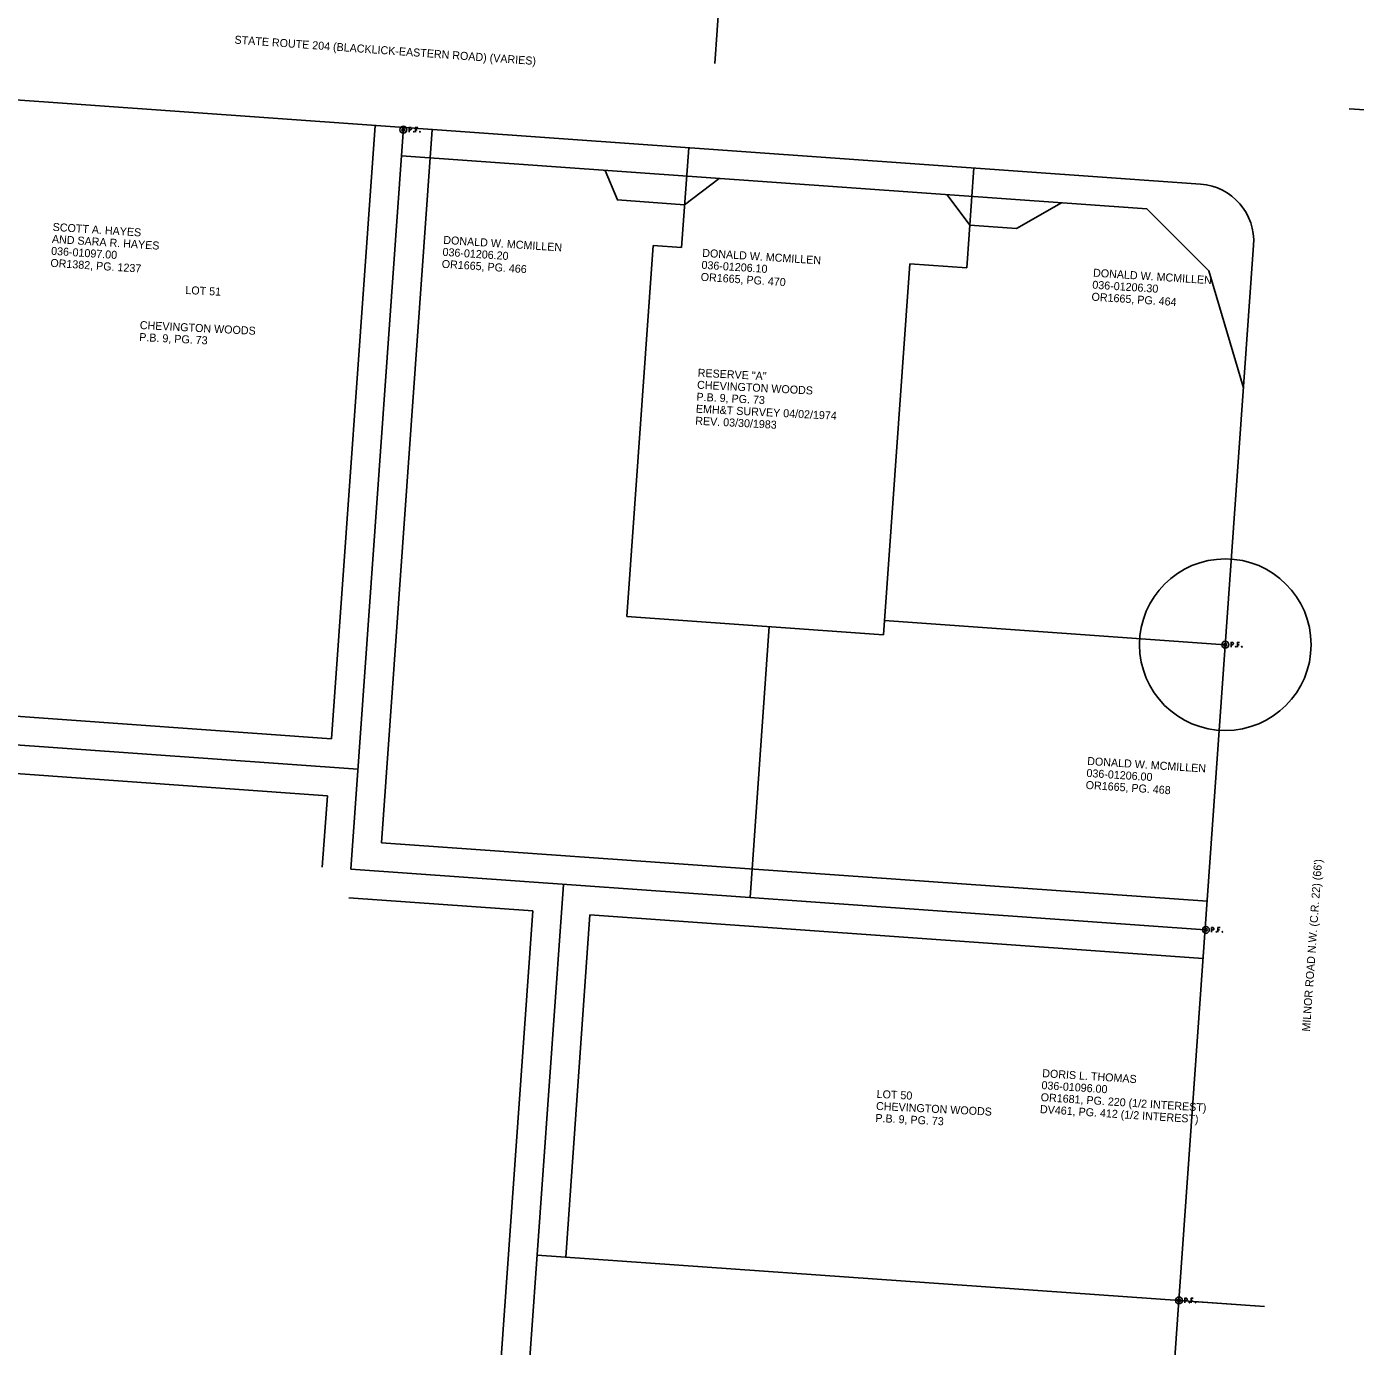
# Model space of a CAD drawing. Extents: x 1898254 to 1901377, y 701554 to 704886.
# Drawn here: x 1899353.1 to 1899817.9, y 702797.1 to 703258.5 of the extents above; entities that cross this region are included whole.
import ezdxf

# ---------------------------------------------------------------- set-up
doc = ezdxf.new("R2010")
doc.units = 0
for name, color, linetype in [('DV_X_Property_Line', 7, 'Continuous'), ('DV_X_Text', 7, 'Continuous'), ('RW_X_CL', 7, 'Continuous'), ('RW_X_Esmt_General', 7, 'Continuous'), ('RW_X_Esmt_SH', 7, 'Continuous'), ('RW_X_Fee_RW', 7, 'Continuous'), ('RW_X_Text', 7, 'Continuous'), ('SC_Scratch1', 7, 'Continuous'), ('SC_Scratch2', 7, 'Continuous'), ('SV_P_Mon_Cells_Set', 7, 'Continuous'), ('SV_X_Mon_Cells_Found', 7, 'Continuous'), ('VG_P_Cells', 7, 'Continuous')]:
    doc.layers.add(name, color=color, linetype=linetype)

msp = doc.modelspace()

# ---------------------------------------------------------------- linework, layer by layer
at = {"layer": 'DV_X_Property_Line'}
for p, q in [((1899466.52, 702963.89), (1899484.96, 703223.29)), ((1899582.23, 703181.28), (1899584.71, 703216.19)), ((1899681.98, 703174.19), (1899684.46, 703209.1)), ((1899563.03, 703052.28), (1899572.25, 703181.99)), ((1899582.23, 703181.28), (1899572.25, 703181.99)), ((1899652.8, 703045.9), (1899662.03, 703175.61)), ((1899681.98, 703174.19), (1899662.03, 703175.61)), ((1899469, 702998.85), (1898413.79, 703073.89)), ((1899652.8, 703045.9), (1899563.03, 703052.28)), ((1899772.41, 703042.41), (1899653.16, 703050.89)), ((1899606.17, 702954), (1899612.91, 703048.74)), ((1899466.52, 702963.89), (1899765.35, 702942.72)), ((1899476.33, 702046.99), (1899540.91, 702958.62)), ((1899531.73, 702829.02), (1899786.09, 702811))]:
    msp.add_line(p, q, dxfattribs=at)
at = {"layer": 'RW_X_CL'}
for p, q in [((1899631.47, 703775.05), (1899593.82, 703245.62)), ((1899815.76, 703229.84), (1901162.17, 703131.42))]:
    msp.add_line(p, q, dxfattribs=at)
at = {"layer": 'RW_X_Esmt_General'}
for p, q in [((1899459.74, 703009.54), (1899474.99, 703224)), ((1899477.2, 702973.16), (1899494.94, 703222.58)), ((1899458.32, 702989.59), (1898413.09, 703063.91)), ((1899459.74, 703009.54), (1899312.22, 703020.03)), ((1899456.54, 702964.6), (1899458.32, 702989.59)), ((1899477.2, 702973.16), (1899766.06, 702952.7)), ((1899465.81, 702953.92), (1899530.23, 702949.35)), ((1899466.62, 702051.43), (1899530.23, 702949.35)), ((1899541.7, 702828.32), (1899550.18, 702947.94)), ((1899550.18, 702947.94), (1899764.64, 702932.75))]:
    msp.add_line(p, q, dxfattribs=at)
at = {"layer": 'RW_X_Esmt_SH'}
msp.add_line((1899746.97, 702683.35), (1899756.17, 702813.12), dxfattribs=at)
at = {"layer": 'RW_X_Fee_RW'}
for p, q in [((1899763.77, 703203.46), (1898449.4, 703296.93)), ((1899756.17, 702813.12), (1899782.31, 703182.1)), ((1899756.17, 702813.12), (1899786.09, 702811))]:
    msp.add_line(p, q, dxfattribs=at)
msp.add_arc((1899762.36, 703183.51), 20, 355.9478, 85.9325, dxfattribs=at)
at = {"layer": 'SC_Scratch1'}
msp.add_circle((1899772.41, 703042.41), 30, dxfattribs=at)
at = {"layer": 'SC_Scratch2'}
msp.add_circle((1899815.76, 703229.84), 1561.35, dxfattribs=at)
at = {"layer": 'SV_P_Mon_Cells_Set'}
for points in [[(1899555.47, 703208.25), (1899559.75, 703197.92), (1899583.29, 703196.24), (1899595.37, 703205.41)], [(1899675.17, 703199.74), (1899683.04, 703189.15), (1899699.4, 703187.99), (1899715.07, 703196.9)]]:
    msp.add_lwpolyline(points, dxfattribs=at)
at = {"layer": 'SV_X_Mon_Cells_Found'}
for points in [[(1899486.9, 703221.67), (1899486.9, 703223.27), (1899487.43, 703223.27), (1899487.49, 703223.25), (1899487.56, 703223.23), (1899487.6, 703223.2), (1899487.63, 703223.18), (1899487.67, 703223.11), (1899487.71, 703223.05), (1899487.73, 703222.95), (1899487.73, 703222.8), (1899487.72, 703222.75), (1899487.7, 703222.67), (1899487.65, 703222.59), (1899487.61, 703222.55), (1899487.58, 703222.52), (1899487.52, 703222.5), (1899487.43, 703222.49), (1899486.9, 703222.49)], [(1899488.55, 703221.88), (1899488.6, 703221.88), (1899488.63, 703221.86), (1899488.67, 703221.8), (1899488.67, 703221.74), (1899488.63, 703221.69), (1899488.6, 703221.67), (1899488.55, 703221.67), (1899488.51, 703221.69), (1899488.48, 703221.74), (1899488.48, 703221.8), (1899488.51, 703221.86), (1899488.55, 703221.88)], [(1899489.91, 703223.27), (1899489.15, 703223.27), (1899489.15, 703221.67)], [(1899489.15, 703222.49), (1899489.69, 703222.49)], [(1899490.69, 703221.88), (1899490.75, 703221.88), (1899490.78, 703221.86), (1899490.82, 703221.8), (1899490.82, 703221.74), (1899490.78, 703221.69), (1899490.75, 703221.67), (1899490.69, 703221.67), (1899490.66, 703221.69), (1899490.63, 703221.74), (1899490.63, 703221.8), (1899490.66, 703221.86), (1899490.69, 703221.88)], [(1899774.41, 703041.61), (1899774.41, 703043.21), (1899774.94, 703043.21), (1899774.99, 703043.19), (1899775.07, 703043.17), (1899775.1, 703043.14), (1899775.13, 703043.12), (1899775.18, 703043.05), (1899775.21, 703042.99), (1899775.23, 703042.89), (1899775.23, 703042.74), (1899775.22, 703042.69), (1899775.2, 703042.61), (1899775.16, 703042.53), (1899775.11, 703042.49), (1899775.08, 703042.46), (1899775.02, 703042.44), (1899774.94, 703042.42), (1899774.41, 703042.42)], [(1899776.05, 703041.82), (1899776.1, 703041.82), (1899776.14, 703041.8), (1899776.17, 703041.74), (1899776.17, 703041.68), (1899776.14, 703041.63), (1899776.1, 703041.61), (1899776.05, 703041.61), (1899776.02, 703041.63), (1899775.98, 703041.68), (1899775.98, 703041.74), (1899776.02, 703041.8), (1899776.05, 703041.82)], [(1899777.42, 703043.21), (1899776.66, 703043.21), (1899776.66, 703041.61)], [(1899776.66, 703042.42), (1899777.2, 703042.42)], [(1899778.2, 703041.82), (1899778.25, 703041.82), (1899778.29, 703041.8), (1899778.32, 703041.74), (1899778.32, 703041.68), (1899778.29, 703041.63), (1899778.25, 703041.61), (1899778.2, 703041.61), (1899778.17, 703041.63), (1899778.13, 703041.68), (1899778.13, 703041.74), (1899778.17, 703041.8), (1899778.2, 703041.82)], [(1899767.59, 702941.91), (1899767.59, 702943.51), (1899768.12, 702943.51), (1899768.18, 702943.49), (1899768.25, 702943.47), (1899768.29, 702943.44), (1899768.32, 702943.42), (1899768.36, 702943.35), (1899768.4, 702943.29), (1899768.42, 702943.19), (1899768.42, 702943.04), (1899768.41, 702942.99), (1899768.39, 702942.91), (1899768.34, 702942.83), (1899768.3, 702942.79), (1899768.27, 702942.76), (1899768.21, 702942.74), (1899768.12, 702942.72), (1899767.59, 702942.72)], [(1899769.24, 702942.12), (1899769.29, 702942.12), (1899769.32, 702942.09), (1899769.36, 702942.04), (1899769.36, 702941.98), (1899769.32, 702941.93), (1899769.29, 702941.91), (1899769.24, 702941.91), (1899769.2, 702941.93), (1899769.17, 702941.98), (1899769.17, 702942.04), (1899769.2, 702942.09), (1899769.24, 702942.12)], [(1899770.6, 702943.51), (1899769.84, 702943.51), (1899769.84, 702941.91)], [(1899769.84, 702942.72), (1899770.38, 702942.72)], [(1899771.38, 702942.12), (1899771.44, 702942.12), (1899771.47, 702942.09), (1899771.51, 702942.04), (1899771.51, 702941.98), (1899771.47, 702941.93), (1899771.44, 702941.91), (1899771.38, 702941.91), (1899771.35, 702941.93), (1899771.32, 702941.98), (1899771.32, 702942.04), (1899771.35, 702942.09), (1899771.38, 702942.12)], [(1899758.2, 702812.32), (1899758.2, 702813.92), (1899758.73, 702813.92), (1899758.79, 702813.91), (1899758.86, 702813.88), (1899758.9, 702813.86), (1899758.93, 702813.83), (1899758.97, 702813.77), (1899759.01, 702813.71), (1899759.03, 702813.6), (1899759.03, 702813.45), (1899759.02, 702813.4), (1899759, 702813.33), (1899758.95, 702813.24), (1899758.91, 702813.2), (1899758.87, 702813.18), (1899758.82, 702813.15), (1899758.73, 702813.14), (1899758.2, 702813.14)], [(1899759.84, 702812.53), (1899759.9, 702812.53), (1899759.93, 702812.51), (1899759.97, 702812.46), (1899759.97, 702812.4), (1899759.93, 702812.34), (1899759.9, 702812.32), (1899759.84, 702812.32), (1899759.81, 702812.34), (1899759.78, 702812.4), (1899759.78, 702812.46), (1899759.81, 702812.51), (1899759.84, 702812.53)], [(1899761.21, 702813.92), (1899760.45, 702813.92), (1899760.45, 702812.32)], [(1899760.45, 702813.14), (1899760.99, 702813.14)], [(1899761.99, 702812.53), (1899762.05, 702812.53), (1899762.08, 702812.51), (1899762.11, 702812.46), (1899762.11, 702812.4), (1899762.08, 702812.34), (1899762.05, 702812.32), (1899761.99, 702812.32), (1899761.96, 702812.34), (1899761.93, 702812.4), (1899761.93, 702812.46), (1899761.96, 702812.51), (1899761.99, 702812.53)]]:
    msp.add_lwpolyline(points, dxfattribs=at)
for centre, radius in [((1899484.91, 703222.47), 1.2), ((1899484.91, 703222.47), 0.495), ((1899772.41, 703042.41), 1.2), ((1899772.41, 703042.41), 0.495), ((1899765.6, 702942.71), 1.2), ((1899765.6, 702942.71), 0.495), ((1899756.2, 702813.12), 1.2), ((1899756.2, 702813.12), 0.495)]:
    msp.add_circle(centre, radius, dxfattribs=at)
at = {"layer": 'VG_P_Cells'}
msp.add_lwpolyline([(1899484.96, 703223.29), (1899484.25, 703213.31), (1899745, 703194.77), (1899766.64, 703173.17), (1899778.77, 703132.21)], dxfattribs=at)

# ---------------------------------------------------------------- texts
at = {"layer": 'DV_X_Text'}
for s, rotation, p in [('SCOTT A. HAYES', 356.3351, (1899362.17, 703187.13)), ('AND SARA R. HAYES', 356.3351, (1899361.91, 703182.94)), ('DONALD W. MCMILLEN', 356.3351, (1899498.81, 703182.59)), ('036-01097.00', 356.3351, (1899361.64, 703178.75)), ('036-01206.20', 356.3351, (1899498.54, 703178.4)), ('DONALD W. MCMILLEN', 356.3351, (1899589.39, 703178.06)), ('OR1382, PG. 1237', 356.3351, (1899361.37, 703174.56)), ('OR1665, PG. 466', 356.3351, (1899498.27, 703174.21)), ('036-01206.10', 356.3351, (1899589.12, 703173.87)), ('OR1665, PG. 470', 356.3351, (1899588.85, 703169.67)), ('DONALD W. MCMILLEN', 356.3351, (1899726.09, 703171.12)), ('LOT 51', 357.0949, (1899408.6, 703165.06)), ('OR1665, PG. 464', 356.3351, (1899725.55, 703162.74)), ('036-01206.30', 356.3351, (1899725.82, 703166.93)), ('P.B. 9, PG. 73', 357.0949, (1899392.46, 703148.62)), ('CHEVINGTON WOODS', 357.0949, (1899392.67, 703152.81)), ('RESERVE "A"', 357.0949, (1899587.81, 703136.13)), ('CHEVINGTON WOODS', 357.0949, (1899587.59, 703131.93)), ('P.B. 9, PG. 73', 357.0949, (1899587.38, 703127.74)), ('EMH&T SURVEY 04/02/1974', 357.0949, (1899587.17, 703123.54)), ('REV. 03/30/1983', 357.0949, (1899586.95, 703119.35)), ('DONALD W. MCMILLEN', 356.3351, (1899724.04, 703000.39)), ('036-01206.00', 356.3351, (1899723.78, 702996.2)), ('OR1665, PG. 468', 356.3351, (1899723.51, 702992.01)), ('DORIS L. THOMAS', 356.3351, (1899708.31, 702891.23)), ('LOT 50', 357.0949, (1899650.39, 702883.96)), ('036-01096.00', 356.3351, (1899708.04, 702887.04)), ('CHEVINGTON WOODS', 357.0949, (1899650.18, 702879.77)), ('OR1681, PG. 220 (1/2 INTEREST)', 356.3351, (1899707.77, 702882.85)), ('P.B. 9, PG. 73', 357.0949, (1899649.96, 702875.57)), ('DV461, PG. 412 (1/2 INTEREST)', 356.3351, (1899707.51, 702878.66))]:
    msp.add_text(s, height=2.8, rotation=rotation, dxfattribs=at).set_placement(p)
at = {"layer": 'RW_X_Text'}
for s, rotation, p in [('STATE ROUTE 204 (BLACKLICK-EASTERN ROAD) (VARIES)', 355.9325, (1899425.77, 703252.61)), ("MILNOR ROAD N.W. (C.R. 22) (66')", 85.9325, (1899802.01, 702907.07))]:
    msp.add_text(s, height=2.8, rotation=rotation, dxfattribs=at).set_placement(p)

doc.saveas('drawing.dxf')
